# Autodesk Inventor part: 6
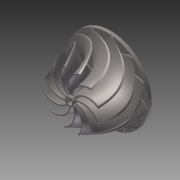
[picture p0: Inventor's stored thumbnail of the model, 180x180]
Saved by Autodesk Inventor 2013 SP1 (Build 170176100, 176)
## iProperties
Created: 2013-05
Part Number: 6
Material: Generic
Document SubType Name: Modeling
Designer: 50384
Density: 1 g/cm^3
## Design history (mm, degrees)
node "compwheel1"
node "compwheel"
node "Base1"
